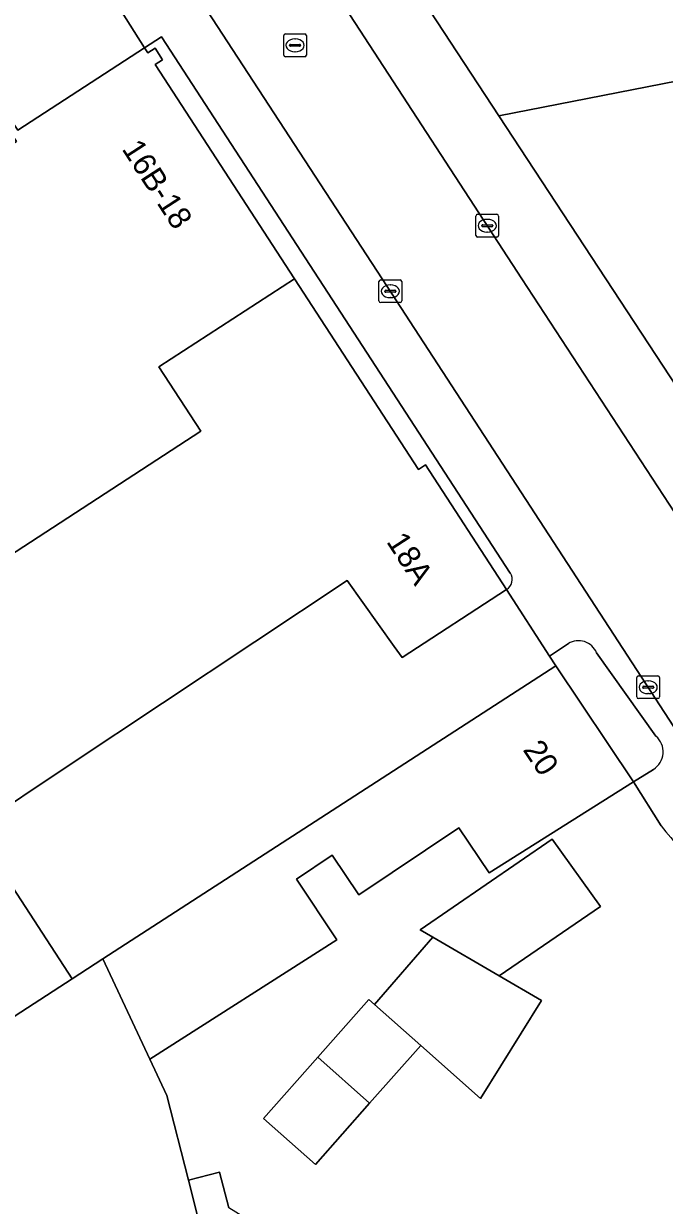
# Model space of a CAD drawing. Extents: x 160856 to 161310, y 384024 to 384878.
# Drawn here: x 161104.4 to 161132.6, y 384459.3 to 384511.2 of the extents above; entities that cross this region are included whole.
import ezdxf

# ---------------------------------------------------------------- set-up
doc = ezdxf.new("R2010")
doc.units = 0
for name, color, linetype in [('IMGEO_Erf', 7, 'Continuous'), ('IMGEO_Kolk', 7, 'Continuous'), ('IMGEO_Pand', 7, 'Continuous'), ('IMGEO_Pand_nummerreeks', 7, 'Continuous'), ('IMGEO_Parkeervlak_open', 7, 'Continuous'), ('IMGEO_Rijbaan_lokaal_open', 7, 'Continuous'), ('IMGEO_Rioolput', 7, 'Continuous'), ('IMGEO_Voetpad_open', 7, 'Continuous')]:
    doc.layers.add(name, color=color, linetype=linetype)

msp = doc.modelspace()

# ---------------------------------------------------------------- linework, layer by layer
at = {"layer": 'IMGEO_Erf'}
for points in [[(161109.703, 384510.154), (161106.274, 384515.593), (161099.532, 384526.285), (161078.632, 384512.731), (161078.403, 384512.582), (161086.528, 384500), (161089.266, 384495.761), (161093.508, 384498.519), (161093.22, 384498.961), (161094.818, 384500), (161104.086, 384506.027), (161103.703, 384506.616), (161103.966, 384506.787), (161104.133, 384506.531)], [(161121.035, 384483.343), (161120.689, 384483.829), (161118.625, 384486.727), (161106.441, 384478.633), (161102.22, 384475.828), (161106.522, 384469.213), (161107.881, 384470.092), (161127.791, 384482.982), (161127.519, 384483.402), (161125.626, 384486.329)], [(161125.309, 384469.346), (161127.161, 384468.265), (161124.487, 384463.959), (161121.857, 384466.285), (161119.608, 384463.747), (161117.225, 384461.059), (161114.944, 384463.081), (161117.326, 384465.769), (161119.573, 384468.304), (161119.814, 384468.091), (161122.388, 384471.052), (161121.834, 384471.375), (161127.639, 384475.357), (161129.763, 384472.401)]]:
    msp.add_lwpolyline(points, close=True, dxfattribs=at)
msp.add_lwpolyline([(161132.428, 384475.949), (161131.213, 384477.878), (161124.863, 384473.882), (161123.536, 384475.861), (161119.134, 384472.91), (161117.964, 384474.654), (161116.386, 384473.596), (161118.168, 384470.938), (161109.942, 384465.677), (161110.685, 384464.086), (161111.639, 384460.369), (161113.009, 384460.72), (161113.412, 384459.149)], dxfattribs=at)
msp.add_arc((161157.697, 384495.628), 32.028, 217.9102, 237.0458, dxfattribs=at)
at = {"layer": 'IMGEO_Kolk'}
for p, q in [((161124.277, 384501.904), (161124.277, 384502.756)), ((161124.352, 384502.83), (161125.204, 384502.83)), ((161125.278, 384502.756), (161125.278, 384501.904)), ((161124.536, 384502.324), (161124.536, 384502.336)), ((161124.974, 384502.287), (161124.576, 384502.287)), ((161124.579, 384502.373), (161124.977, 384502.373)), ((161124.765, 384502.61), (161124.79, 384502.61)), ((161125.02, 384502.336), (161125.02, 384502.324)), ((161125.204, 384501.83), (161124.352, 384501.83)), ((161124.788, 384502.05), (161124.763, 384502.05)), ((161120.018, 384499.022), (161120.018, 384499.874)), ((161120.093, 384499.948), (161120.945, 384499.948)), ((161120.506, 384499.728), (161120.531, 384499.728)), ((161121.019, 384499.874), (161121.019, 384499.022)), ((161120.277, 384499.442), (161120.277, 384499.454)), ((161120.715, 384499.405), (161120.317, 384499.405)), ((161120.32, 384499.491), (161120.718, 384499.491)), ((161120.529, 384499.168), (161120.504, 384499.168)), ((161120.761, 384499.454), (161120.761, 384499.442)), ((161120.945, 384498.948), (161120.093, 384498.948)), ((161131.353, 384481.609), (161131.353, 384482.461)), ((161131.428, 384482.535), (161132.28, 384482.535)), ((161132.354, 384482.461), (161132.354, 384481.609)), ((161131.612, 384482.029), (161131.612, 384482.041)), ((161132.05, 384481.992), (161131.652, 384481.992)), ((161131.655, 384482.078), (161132.053, 384482.078)), ((161131.841, 384482.315), (161131.866, 384482.315)), ((161132.096, 384482.041), (161132.096, 384482.029)), ((161132.28, 384481.535), (161131.428, 384481.535)), ((161131.864, 384481.755), (161131.839, 384481.755))]:
    msp.add_line(p, q, dxfattribs=at)
for points in [[(161124.277, 384501.904), (161124.277, 384502.756)], [(161124.352, 384502.83), (161125.204, 384502.83)], [(161125.278, 384502.756), (161125.278, 384501.904)], [(161125.204, 384501.83), (161124.352, 384501.83)], [(161120.018, 384499.022), (161120.018, 384499.874)], [(161120.093, 384499.948), (161120.945, 384499.948)], [(161121.019, 384499.874), (161121.019, 384499.022)], [(161120.945, 384498.948), (161120.093, 384498.948)], [(161131.353, 384481.609), (161131.353, 384482.461)], [(161131.428, 384482.535), (161132.28, 384482.535)], [(161132.354, 384482.461), (161132.354, 384481.609)], [(161132.28, 384481.535), (161131.428, 384481.535)]]:
    msp.add_lwpolyline(points, dxfattribs=at)
for centre, radius, start, end in [((161124.354, 384502.754), 0.0765, 91.552, 178.448), ((161124.354, 384502.754), 0.0765, 91.552, 178.448), ((161125.202, 384502.754), 0.0765, 1.552, 88.448), ((161125.202, 384502.754), 0.0765, 1.552, 88.448), ((161124.576, 384502.333), 0.0403, 85.8775, 175.7526), ((161124.573, 384502.323), 0.0366, 178.938, 274.7102), ((161124.977, 384502.33), 0.043, 264.8664, 352.4533), ((161124.981, 384502.335), 0.0386, 1.7309, 96.639), ((161124.354, 384501.906), 0.0765, 181.552, 268.448), ((161124.354, 384501.906), 0.0765, 181.552, 268.448), ((161125.202, 384501.906), 0.0765, 271.552, 358.448), ((161125.202, 384501.906), 0.0765, 271.552, 358.448), ((161120.095, 384499.872), 0.0765, 91.552, 178.448), ((161120.095, 384499.872), 0.0765, 91.552, 178.448), ((161120.943, 384499.872), 0.0765, 1.552, 88.448), ((161120.943, 384499.872), 0.0765, 1.552, 88.448), ((161120.317, 384499.451), 0.0403, 85.8775, 175.7526), ((161120.314, 384499.441), 0.0366, 178.938, 274.7102), ((161120.718, 384499.448), 0.043, 264.8664, 352.4533), ((161120.722, 384499.453), 0.0386, 1.7309, 96.639), ((161120.095, 384499.024), 0.0765, 181.552, 268.448), ((161120.095, 384499.024), 0.0765, 181.552, 268.448), ((161120.943, 384499.024), 0.0765, 271.552, 358.448), ((161120.943, 384499.024), 0.0765, 271.552, 358.448), ((161131.43, 384482.459), 0.0765, 91.552, 178.448), ((161131.43, 384482.459), 0.0765, 91.552, 178.448), ((161132.278, 384482.459), 0.0765, 1.552, 88.448), ((161132.278, 384482.459), 0.0765, 1.552, 88.448), ((161131.652, 384482.038), 0.0403, 85.8775, 175.7526), ((161131.649, 384482.028), 0.0366, 178.938, 274.7102), ((161132.053, 384482.035), 0.043, 264.8664, 352.4533), ((161132.057, 384482.04), 0.0386, 1.7309, 96.639), ((161131.43, 384481.611), 0.0765, 181.552, 268.448), ((161131.43, 384481.611), 0.0765, 181.552, 268.448), ((161132.278, 384481.611), 0.0765, 271.552, 358.448), ((161132.278, 384481.611), 0.0765, 271.552, 358.448)]:
    msp.add_arc(centre, radius, start, end, dxfattribs=at)
for centre, major_axis, ratio, start_param, end_param in [((161124.764, 384502.33), (-0.387, 0.002), 0.722429, 4.712389, 7.853982), ((161124.789, 384502.33), (-0.39, 0.002), 0.717154, 1.570796, 4.712389), ((161120.505, 384499.448), (-0.387, 0.002), 0.722429, 4.712389, 7.853982), ((161120.53, 384499.448), (-0.39, 0.002), 0.717154, 1.570796, 4.712389), ((161131.84, 384482.035), (-0.387, 0.002), 0.722429, 4.712389, 7.853982), ((161131.865, 384482.035), (-0.39, 0.002), 0.717154, 1.570796, 4.712389)]:
    msp.add_ellipse(centre, major_axis=major_axis, ratio=ratio, start_param=start_param, end_param=end_param, dxfattribs=at)
at = {"layer": 'IMGEO_Pand'}
for points in [[(161118.791, 384517.525), (161118.6, 384517.368), (161125.289, 384507.167), (161139.008, 384509.838), (161145.671, 384511.135), (161146.897, 384522.997)], [(161125.289, 384507.167), (161129.988, 384500), (161136.26, 384490.435), (161143.676, 384491.742), (161144.181, 384496.717), (161144.52, 384500), (161145.671, 384511.135), (161139.008, 384509.838)], [(161086.57, 384481.163), (161088.869, 384477.676), (161097.269, 384483.441), (161101.448, 384486.31), (161112.184, 384493.292), (161110.342, 384496.125), (161116.298, 384500), (161110.176, 384509.414), (161110.505, 384509.628), (161110.173, 384510.137), (161109.85, 384509.927), (161109.703, 384510.154), (161104.133, 384506.531), (161103.966, 384506.787), (161103.703, 384506.616), (161104.086, 384506.027), (161094.818, 384500), (161093.22, 384498.961), (161093.508, 384498.519), (161089.266, 384495.761), (161095.125, 384486.687)], [(161116.298, 384500), (161110.342, 384496.125), (161112.184, 384493.292), (161101.448, 384486.31), (161097.269, 384483.441), (161102.22, 384475.828), (161106.441, 384478.633), (161118.625, 384486.727), (161120.689, 384483.829), (161121.035, 384483.343), (161125.626, 384486.329), (161122.06, 384491.813), (161121.753, 384491.613)], [(161097.209, 384465.039), (161098.067, 384463.739), (161106.522, 384469.213), (161102.22, 384475.828), (161097.269, 384483.441), (161088.869, 384477.676)], [(161107.881, 384470.092), (161109.942, 384465.677), (161118.168, 384470.938), (161116.386, 384473.596), (161117.964, 384474.654), (161119.134, 384472.91), (161123.536, 384475.861), (161124.863, 384473.882), (161131.213, 384477.878), (161127.791, 384482.982)], [(161129.763, 384472.401), (161127.639, 384475.357), (161121.834, 384471.375), (161122.388, 384471.052), (161125.309, 384469.346)], [(161125.309, 384469.346), (161122.388, 384471.052), (161119.814, 384468.091), (161121.857, 384466.285), (161124.487, 384463.959), (161127.161, 384468.265)], [(161112.248, 384457.995), (161112.06, 384458.73), (161111.639, 384460.369), (161110.685, 384464.086), (161109.942, 384465.677), (161107.881, 384470.092), (161106.522, 384469.213), (161098.067, 384463.739), (161097.209, 384465.039), (161091.365, 384462.502), (161095.906, 384452.045), (161094.201, 384451.035), (161094.568, 384450.014), (161097.341, 384442.312), (161099.363, 384436.033), (161109.228, 384435.688), (161110.053, 384441.789), (161110.917, 384448.182)], [(161119.814, 384468.091), (161119.573, 384468.304), (161117.326, 384465.769), (161119.608, 384463.747), (161121.857, 384466.285)], [(161119.608, 384463.747), (161117.326, 384465.769), (161114.944, 384463.081), (161117.225, 384461.059)]]:
    msp.add_lwpolyline(points, close=True, dxfattribs=at)
at = {"layer": 'IMGEO_Parkeervlak_open'}
for points in [[(161129.988, 384500), (161125.289, 384507.167), (161118.6, 384517.368), (161118.791, 384517.525), (161116.865, 384520.568), (161116.568, 384520.434), (161110.014, 384530.492), (161110.201, 384530.752), (161108.284, 384533.515), (161108.586, 384536.5), (161108.888, 384539.484), (161105.202, 384539.856), (161106.17, 384549.359), (161111.404, 384564.308), (161113.261, 384569.256), (161118.045, 384583.164), (161121.366, 384592.819), (161123.534, 384599.122), (161124.003, 384603.832), (161125.354, 384617.415)], [(161147.548, 384467.735), (161146.601, 384468.302), (161145.038, 384469.237), (161143.348, 384470.277), (161140.555, 384472.281), (161137.951, 384474.526), (161135.559, 384476.994), (161133.535, 384479.496), (161133.397, 384479.667), (161120.155, 384500), (161106.333, 384521.187)], [(161106.274, 384515.593), (161109.703, 384510.154), (161110.453, 384510.641), (161117.372, 384500), (161125.793, 384487.05)], [(161118.543, 384511.891), (161126.296, 384500), (161135.763, 384485.512)], [(161136.26, 384490.435), (161129.988, 384500)], [(161125.626, 384486.329), (161127.519, 384483.402), (161128.344, 384483.955)], [(161129.587, 384483.55), (161132.193, 384479.881)], [(161132.085, 384478.427), (161131.213, 384477.878), (161132.428, 384475.949)]]:
    msp.add_lwpolyline(points, dxfattribs=at)
for centre, radius, start, end in [((161125.36, 384486.771), 0.516, 301.0894, 32.8285), ((161128.794, 384483.227), 0.856, 22.174, 121.7322), ((161131.61, 384479.193), 0.902, 301.8096, 49.6943), ((161157.697, 384495.628), 32.028, 217.9102, 237.0458)]:
    msp.add_arc(centre, radius, start, end, dxfattribs=at)
at = {"layer": 'IMGEO_Rijbaan_lokaal_open'}
for points in [[(161106.333, 384521.187), (161120.155, 384500), (161133.397, 384479.667)], [(161159.505, 384476.619), (161149.357, 384478.328), (161143.93, 384479.281), (161143.205, 384479.449), (161142.726, 384479.56), (161141.89, 384479.842), (161141.004, 384480.229), (161140.156, 384480.693), (161139.353, 384481.23), (161138.602, 384481.838), (161137.907, 384482.51), (161137.276, 384483.241), (161136.712, 384484.026), (161136.487, 384484.329), (161135.763, 384485.512), (161126.296, 384500), (161118.543, 384511.891)]]:
    msp.add_lwpolyline(points, dxfattribs=at)
at = {"layer": 'IMGEO_Rioolput'}
for p, q in [((161115.829, 384509.835), (161115.829, 384510.687)), ((161115.904, 384510.761), (161116.756, 384510.761)), ((161116.317, 384510.541), (161116.342, 384510.541)), ((161116.83, 384510.687), (161116.83, 384509.835)), ((161116.088, 384510.255), (161116.088, 384510.267)), ((161116.526, 384510.218), (161116.128, 384510.218)), ((161116.131, 384510.304), (161116.529, 384510.304)), ((161116.572, 384510.267), (161116.572, 384510.255)), ((161116.756, 384509.761), (161115.904, 384509.761)), ((161116.34, 384509.981), (161116.315, 384509.981))]:
    msp.add_line(p, q, dxfattribs=at)
for points in [[(161115.829, 384509.835), (161115.829, 384510.687)], [(161115.904, 384510.761), (161116.756, 384510.761)], [(161116.83, 384510.687), (161116.83, 384509.835)], [(161116.756, 384509.761), (161115.904, 384509.761)]]:
    msp.add_lwpolyline(points, dxfattribs=at)
for centre, radius, start, end in [((161115.906, 384510.685), 0.0765, 91.552, 178.448), ((161115.906, 384510.685), 0.0765, 91.552, 178.448), ((161116.754, 384510.685), 0.0765, 1.552, 88.448), ((161116.754, 384510.685), 0.0765, 1.552, 88.448), ((161116.128, 384510.264), 0.0403, 85.8775, 175.7526), ((161116.125, 384510.254), 0.0366, 178.938, 274.7102), ((161116.529, 384510.261), 0.043, 264.8664, 352.4533), ((161116.533, 384510.266), 0.0386, 1.7309, 96.639), ((161115.906, 384509.837), 0.0765, 181.552, 268.448), ((161115.906, 384509.837), 0.0765, 181.552, 268.448), ((161116.754, 384509.837), 0.0765, 271.552, 358.448), ((161116.754, 384509.837), 0.0765, 271.552, 358.448)]:
    msp.add_arc(centre, radius, start, end, dxfattribs=at)
for centre, major_axis, ratio, start_param, end_param in [((161116.316, 384510.261), (-0.387, 0.002), 0.722429, 4.712389, 7.853982), ((161116.341, 384510.261), (-0.39, 0.002), 0.717154, 1.570796, 4.712389)]:
    msp.add_ellipse(centre, major_axis=major_axis, ratio=ratio, start_param=start_param, end_param=end_param, dxfattribs=at)
at = {"layer": 'IMGEO_Voetpad_open'}
for points in [[(161125.793, 384487.05), (161117.372, 384500), (161110.453, 384510.641), (161109.703, 384510.154), (161109.85, 384509.927), (161110.173, 384510.137), (161110.505, 384509.628), (161110.176, 384509.414), (161116.298, 384500), (161121.753, 384491.613), (161122.06, 384491.813), (161125.626, 384486.329)], [(161128.344, 384483.955), (161127.519, 384483.402), (161127.791, 384482.982), (161131.213, 384477.878), (161132.085, 384478.427)], [(161132.193, 384479.881), (161129.587, 384483.55)]]:
    msp.add_lwpolyline(points, dxfattribs=at)
msp.add_lwpolyline([(161113.412, 384459.149), (161113.009, 384460.72), (161111.639, 384460.369), (161112.06, 384458.73), (161123.094, 384451.701), (161126.8, 384449.413), (161129.395, 384447.811), (161132.818, 384445.698), (161140.923, 384440.635), (161141.582, 384441.69)], close=True, dxfattribs=at)
for centre, radius, start, end in [((161125.36, 384486.771), 0.516, 301.0894, 32.8285), ((161128.794, 384483.227), 0.856, 22.174, 121.7322), ((161131.61, 384479.193), 0.902, 301.8096, 49.6943)]:
    msp.add_arc(centre, radius, start, end, dxfattribs=at)

# ---------------------------------------------------------------- texts
at = {"layer": 'IMGEO_Pand_nummerreeks'}
for s, rotation, p in [('16B-18', 302.927, (161108.687, 384505.707)), ('18A', 302.9903, (161120.319, 384488.439)), ('20', 303.8401, (161126.319, 384479.287))]:
    msp.add_text(s, height=1, rotation=rotation, dxfattribs=at).set_placement(p)

doc.saveas('drawing.dxf')
